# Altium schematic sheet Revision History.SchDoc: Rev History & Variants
size 431 x 279 mm; Date: Not shown in title block; ApprovedBy: Not shown in title block; CheckedBy: Not shown in title block; Author: Not shown in title block; CompanyName: Not shown in title block; Engineer: Not shown in title block; Organization: Not shown in title block; Address1: Not shown in title block; Address2: Not shown in title block; Address3: Not shown in title block; Address4: Not shown in title block; DocumentNumber: 5; Revision: Use project parameter SCH_Rev; SheetNumber: 15; SheetTotal: 15; PageSetup: Record=PageOptions¦CenterHorizontal=True¦CenterVertical=True¦PrintScale=1.00¦XCorrection=1.00¦YCorrection=1.00¦PrintKind=0¦BorderSize=5000000¦LeftOffset=0¦BottomOffset=0¦Orientation=2¦PaperLength=1000¦PaperWidth=1000¦Scale=100¦PaperSource=15¦PrintQuality=600¦MediaType=1¦DitherType=10¦PaperKind=Letter¦PrintScaleMode=1
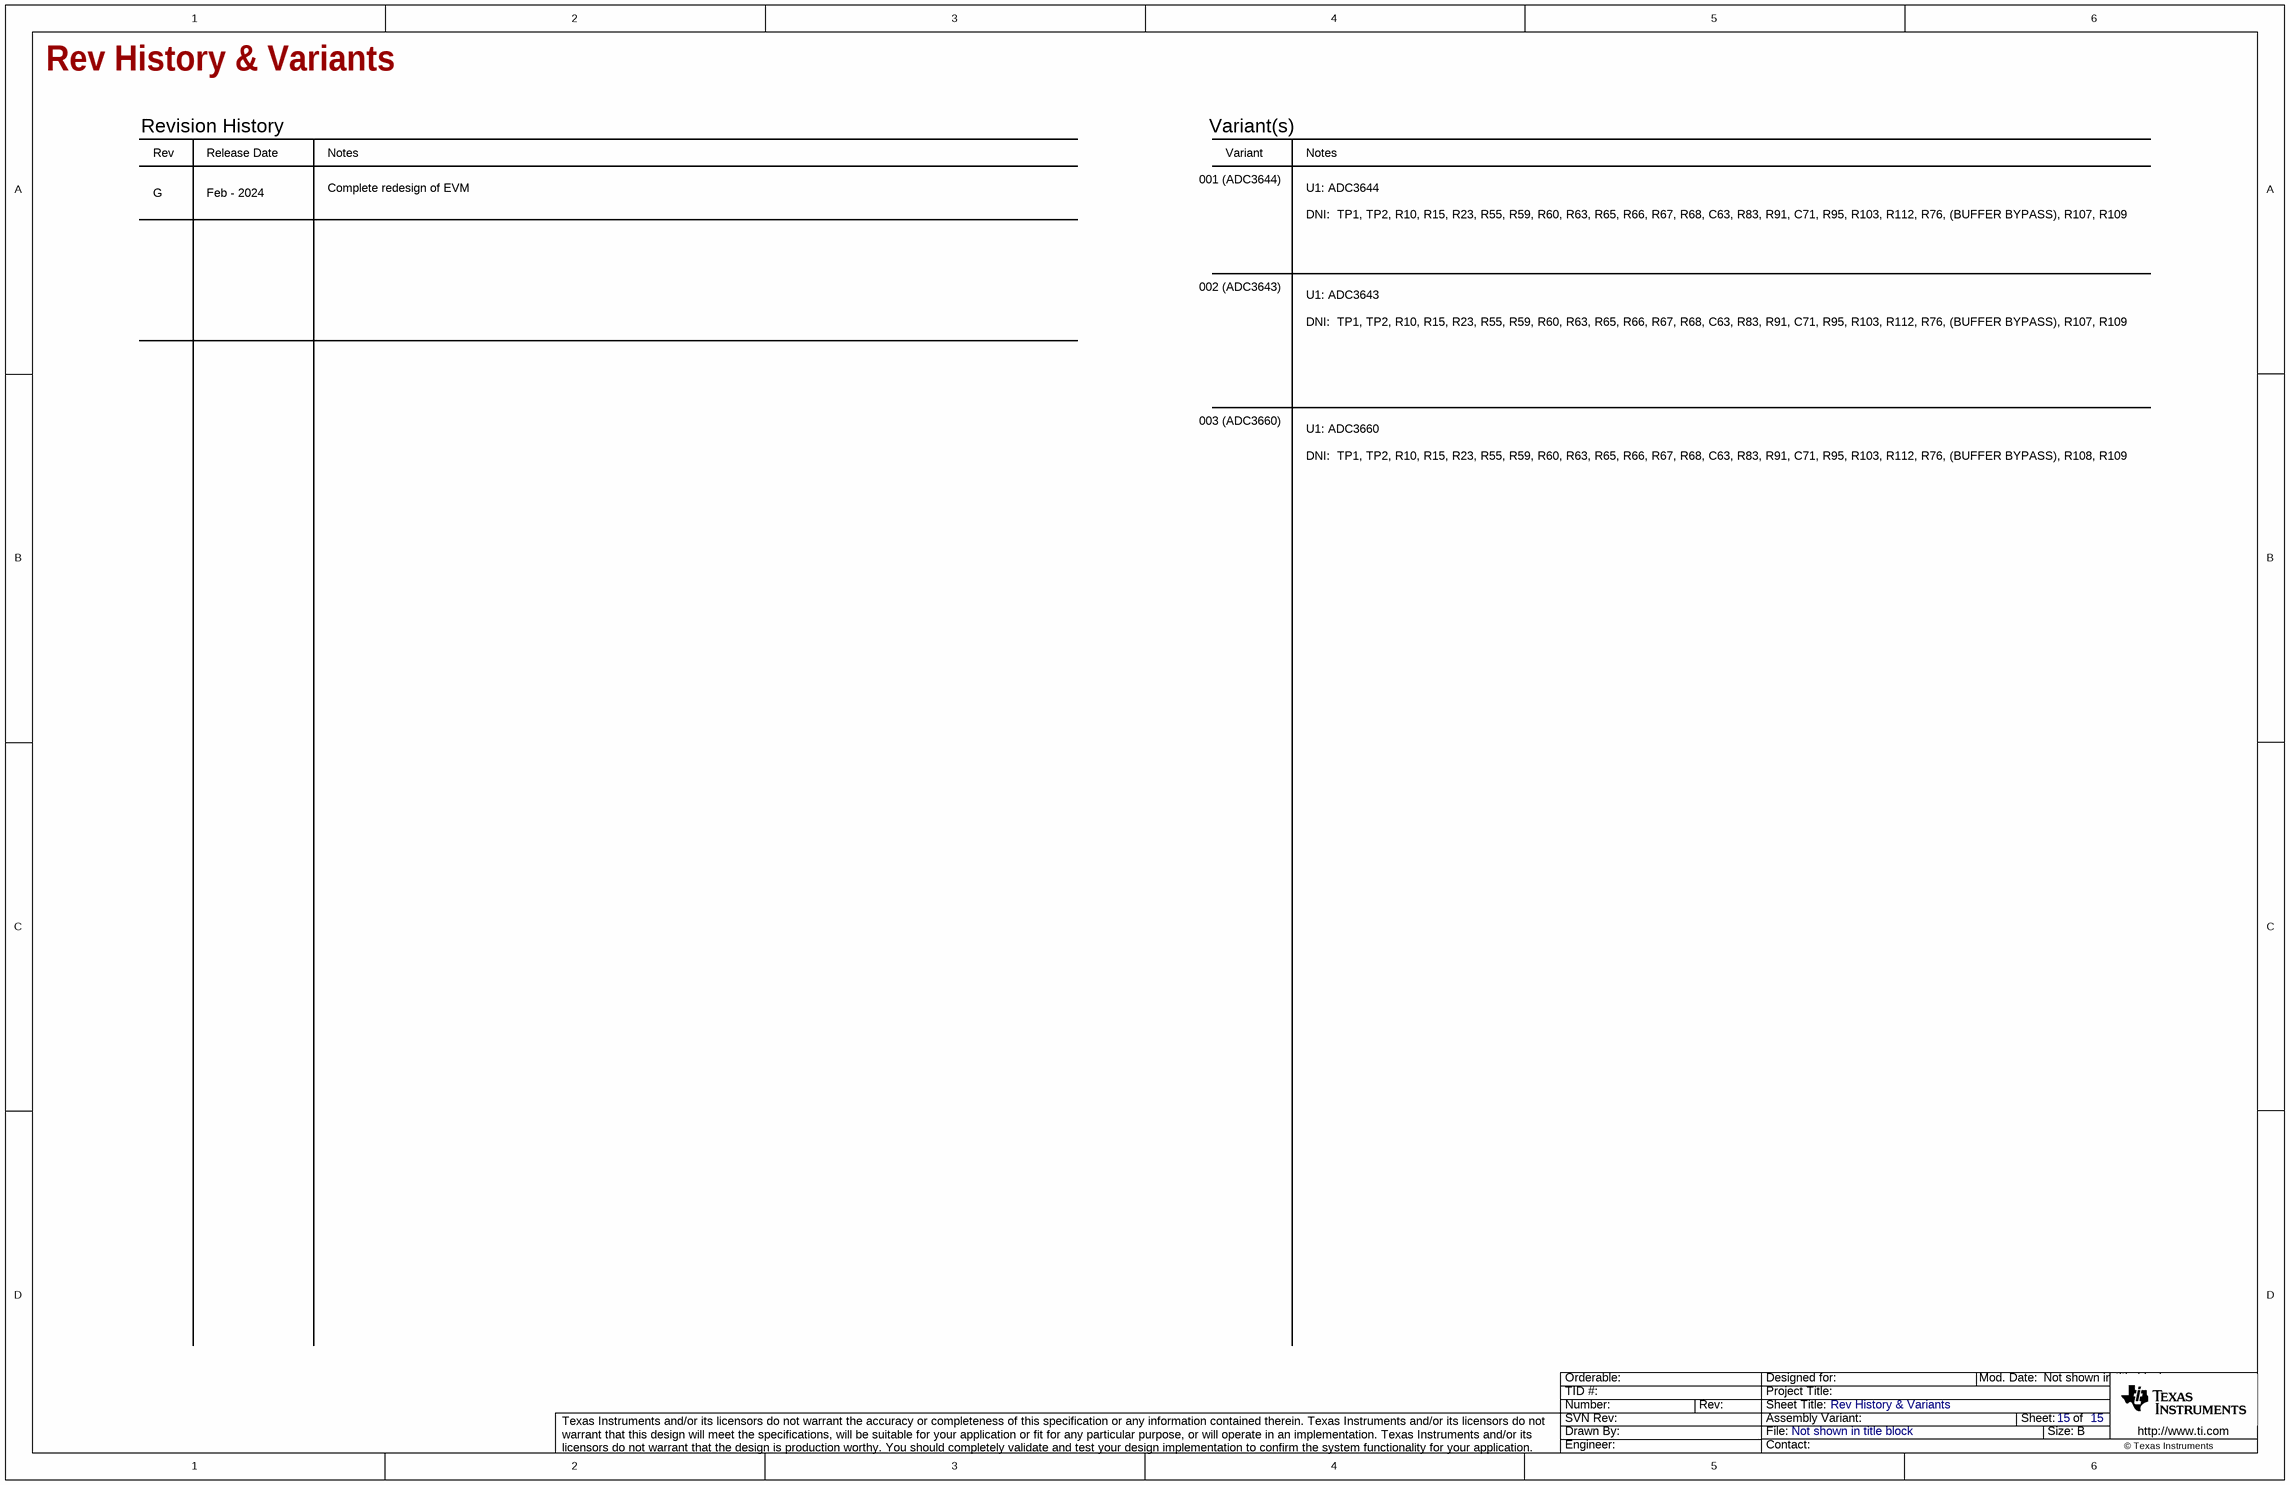
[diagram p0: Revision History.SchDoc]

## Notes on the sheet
- Rev
- Release Date
- Revision History
- Notes
- Variant
- Variant(s)
- G
- Feb - 2024
- Complete redesign of EVM
- 001 (ADC3644)
- 002 (ADC3643)
- U1: ADC3644
  DNI:  TP1, TP2, R10, R15, R23, R55, R59, R60, R63, R65, R66, R67, R68, C63, R83, R91, C71, R95, R103, R112, R76, (BUFFER BYPASS), R107, R109
- U1: ADC3643
  DNI:  TP1, TP2, R10, R15, R23, R55, R59, R60, R63, R65, R66, R67, R68, C63, R83, R91, C71, R95, R103, R112, R76, (BUFFER BYPASS), R107, R109
- 003 (ADC3660)
- U1: ADC3660
  DNI:  TP1, TP2, R10, R15, R23, R55, R59, R60, R63, R65, R66, R67, R68, C63, R83, R91, C71, R95, R103, R112, R76, (BUFFER BYPASS), R108, R109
